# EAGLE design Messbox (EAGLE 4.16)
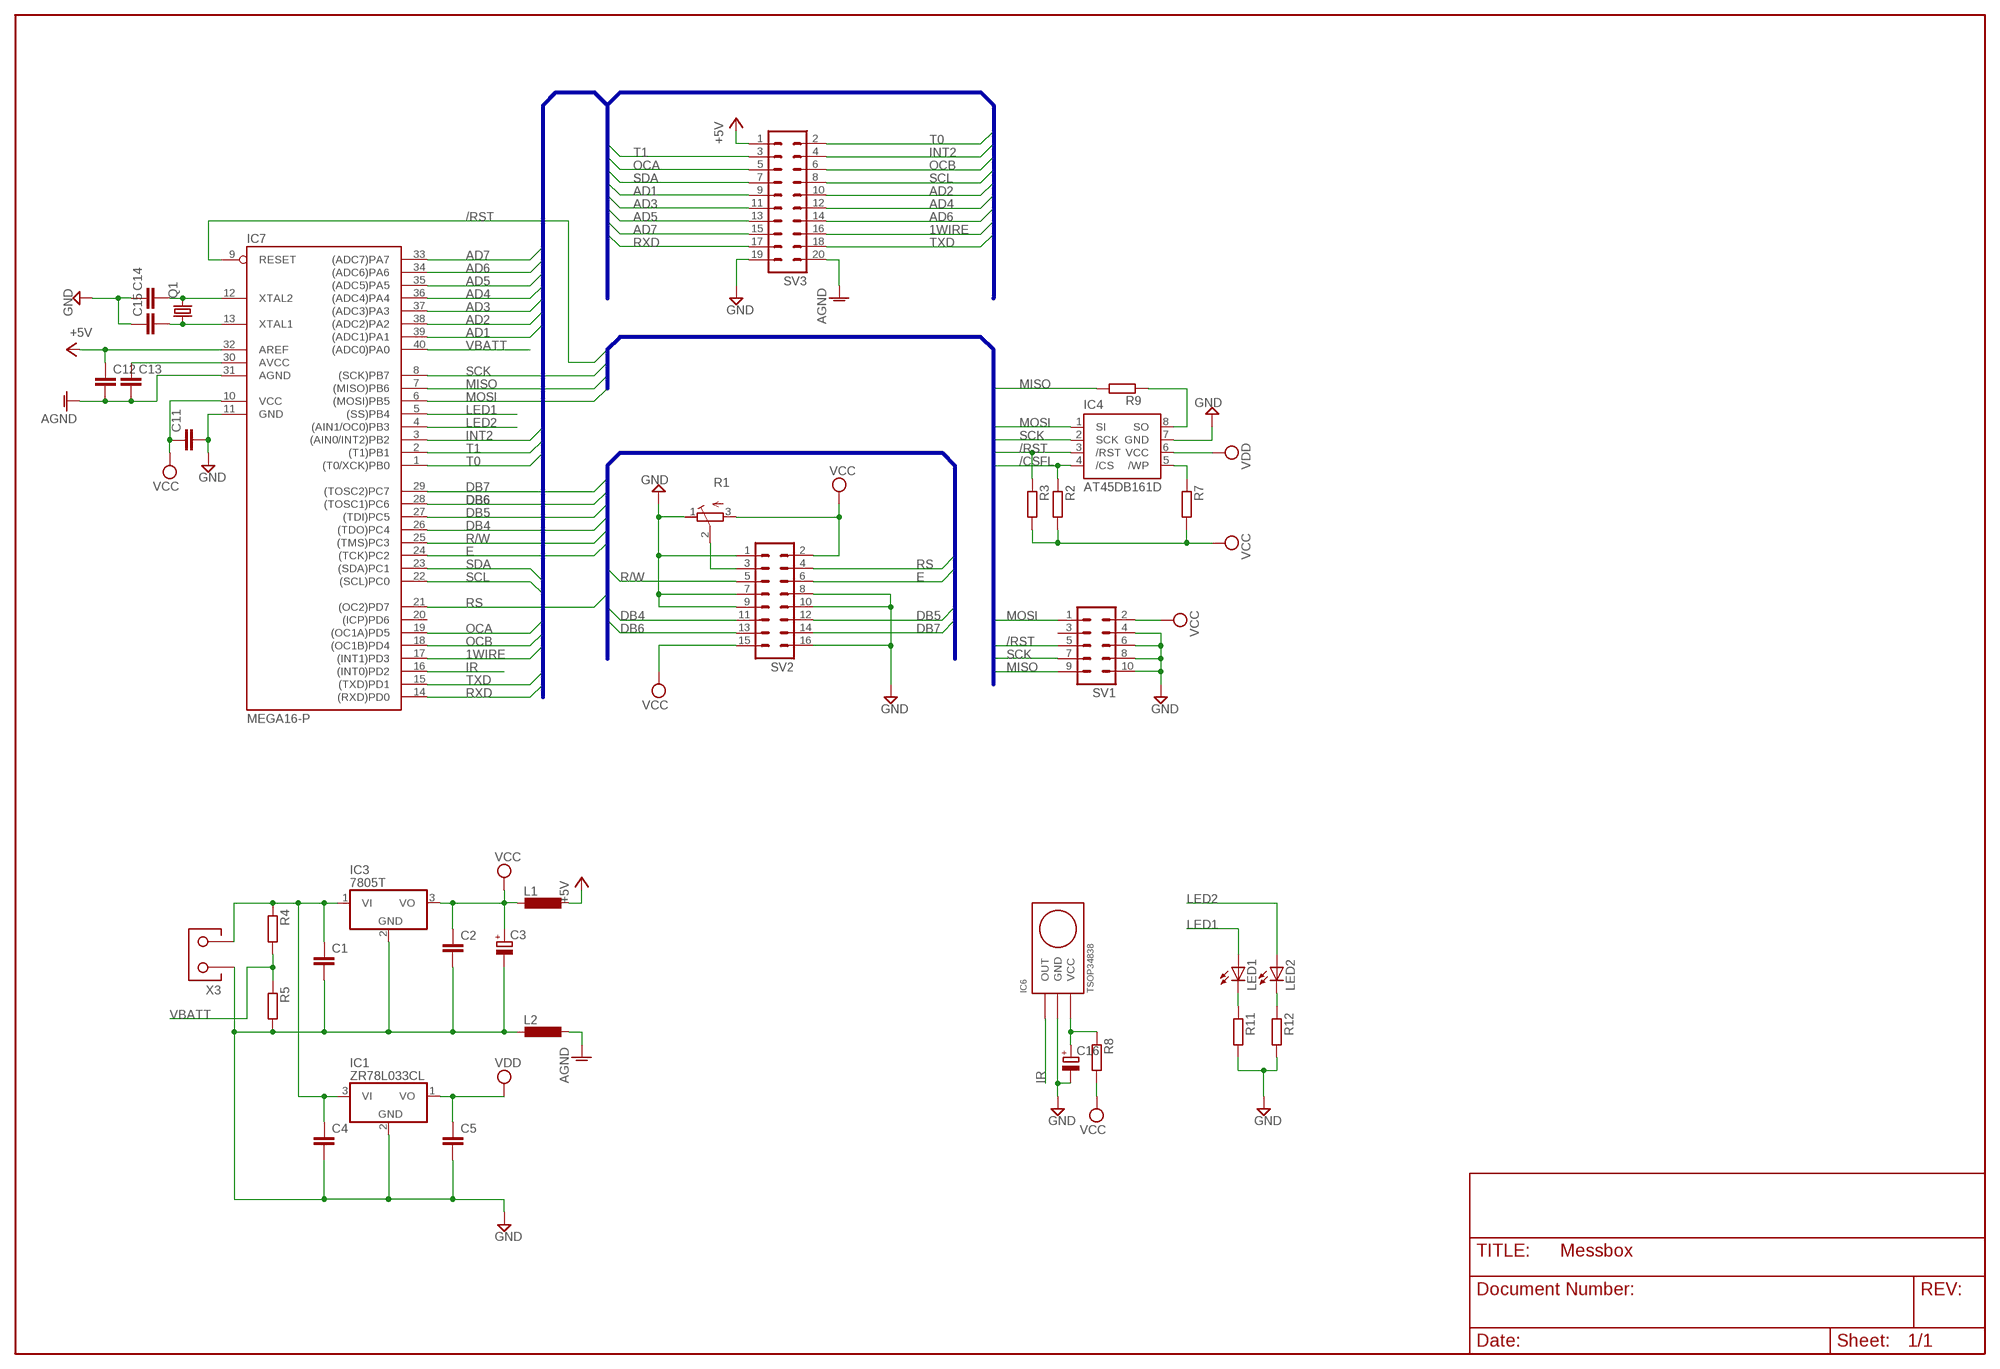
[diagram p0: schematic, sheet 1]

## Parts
C1  C-EUC1206K  [C1206K]
C2  C-EUC1206K  [C1206K]
C3  CPOL-EUE2.5-5  [E2,5-5]
C4  C-EUC1206K  [C1206K]
C5  C-EUC1206K  [C1206K]
C11  C-EUC1206K  [C1206K]
C12  C-EUC1206K  [C1206K]
C13  C-EUC1206K  [C1206K]
C14  C-EUC1206K  [C1206K]
C15  C-EUC1206K  [C1206K]
C16  CPOL-EUE2.5-5  [E2,5-5]
IC1  ZR78L033CL  [TO92]
IC3  7805T  [TO220H]
IC4  AT45DB161D  [SOIC8]
IC6  TSOP34838  [TSOP348]
IC7  MEGA16-P  [DIL40]
L1  L-EU0207/10  [0207/10]
L2  L-EU0207/10  [0207/10]
LED1  LED5MM  [LED5MM]
LED2  LED5MM  [LED5MM]
Q1  CRYTALHC49U-V  [HC49U-V]
R1  R-TRIMMT93YB  [RTRIMT93YB]
R2  R-EU_0207/10  [0207/10]
R3  R-EU_0207/10  [0207/10]
R4  R-EU_0207/10  [0207/10]
R5  R-EU_0207/10  [0207/10]
R7  R-EU_0207/10  [0207/10]
R8  R-EU_0207/10  [0207/10]
R9  R-EU_0207/10  [0207/10]
R11  R-EU_0207/10  [0207/10]
R12  R-EU_0207/10  [0207/10]
SV1  ML10  [ML10]
SV2  ML16  [ML16]
SV3  ML20  [ML20]
X3  AKL-2_3,5  [AKL-2_3,5]

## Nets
1WIRE: IC7.17((INT1)PD3) SV3.16
+5V: C12.1 IC7.32(AREF) L1.1 SV3.1
/CSFL: IC4.4(/CS) R2.1
/RST: IC4.3(/RST) IC7.9(RESET) R3.1 SV1.5
AD1: IC7.39((ADC1)PA1) SV3.9
AD2: IC7.38((ADC2)PA2) SV3.10
AD3: IC7.37((ADC3)PA3) SV3.11
AD4: IC7.36((ADC4)PA4) SV3.12
AD5: IC7.35((ADC5)PA5) SV3.13
AD6: IC7.34((ADC6)PA6) SV3.14
AD7: IC7.33((ADC7)PA7) SV3.15
AGND: C12.2 C13.2 IC7.31(AGND) L2.1 SV3.20
DB4: IC7.26((TDO)PC4) SV2.11
DB5: IC7.27((TDI)PC5) SV2.12
DB6: IC7.28((TOSC1)PC6) SV2.13
DB7: IC7.29((TOSC2)PC7) SV2.14
E: IC7.24((TCK)PC2) SV2.6
GND: C1.2 C2.2 C3.- C4.2 C5.2 C11.2 C14.1 C15.1 C16.- IC1.2(GND) IC3.2(GND) IC4.7(GND) IC6.P$2(GND) IC7.11(GND) L2.2 R1.1(A) R5.2 R11.2 R12.2 SV1.4 SV1.6 SV1.8 SV1.10 SV2.1 SV2.7 SV2.8 SV2.9 SV2.10 SV2.16 SV3.19 X3.P$1
INT2: IC7.3((AIN0/INT2)PB2) SV3.4
IR: IC6.P$1(OUT) IC7.16((INT0)PD2)
LED1: IC7.5((SS)PB4) LED1.A
LED2: IC7.4((AIN1/OC0)PB3) LED2.A
MISO: IC7.7((MISO)PB6) R9.2 SV1.9
MOSI: IC4.1(SI) IC7.6((MOSI)PB5) SV1.1
N$1: LED2.K(C) R12.1
N$3: LED1.K(C) R11.1
N$4: R1.2(S) SV2.3
N$14: IC4.8(SO) R9.1
N$18: C16.+ IC6.P$3(VCC) R8.1
N$20: C1.1 C4.1 IC1.3(VI) IC3.1(VI) R4.1 X3.P$2
N$21: C15.2 IC7.13(XTAL1) Q1.1
N$23: C14.2 IC7.12(XTAL2) Q1.2
N$42: IC4.5(/WP) R7.1
N$46: C13.1 IC7.30(AVCC)
OCA: IC7.19((OC1A)PD5) SV3.5
OCB: IC7.18((OC1B)PD4) SV3.6
R/W: IC7.25((TMS)PC3) SV2.5
RS: IC7.21((OC2)PD7) SV2.4
RXD: IC7.14((RXD)PD0) SV3.17
SCK: IC4.2(SCK) IC7.8((SCK)PB7) SV1.7
SCL: IC7.22((SCL)PC0) SV3.8
SDA: IC7.23((SDA)PC1) SV3.7
T0: IC7.1((T0/XCK)PB0) SV3.2
T1: IC7.2((T1)PB1) SV3.3
TXD: IC7.15((TXD)PD1) SV3.18
VBATT: IC7.40((ADC0)PA0) R4.2 R5.1
VCC: C2.1 C3.+ C11.1 IC3.3(VO) IC7.10(VCC) L1.2 R1.3(E) R2.2 R3.2 R7.2 R8.2 SV1.2 SV2.2 SV2.15
VDD: C5.1 IC1.1(VO) IC4.6(VCC)
Unconnected: IC7.20((ICP)PD6) SV1.3

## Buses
MOSI,MISO,SCK,/RST,/CSFL
RS,R/W,E,DB[4..7]
AD[0..7],OCA,OCB,RXD,TXD,SDA,SCL,1WIRE,T0,T1,INT2

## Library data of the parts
C1 C2 C4 C5 C11-C15 = rcl:C-EU: CAPACITOR, European symbol
C3 C16 = rcl:CPOL-EU: POLARIZED CAPACITOR, European symbol
IC1 = 0mylib:ZR78L033C: Positive VOLTAGE REGULATOR Source: http://cache.national.com/ds/LM/LM78L05.pdf http://www.fairchildsemi.com/ds/LM/LM7805.pdf
IC3 = linear:78*: Positive VOLTAGE REGULATOR
IC4 = 0mylib:AT45DB161D
IC6 = 0mylib:TSOP34838
IC7 = avr:MEGA16-P: MICROCONTROLLER 16 Kbytes FLASH 1 kbytes SRAM 512 bytes EEPROM USART 8-channel 10 bit ADC
L1 L2 = rcl:L-EU: INDUCTOR, European symbol
LED1 LED2 = led:LED: LED
Q1 = crystal:CRYTAL: CRYSTAL
R1 = rcl:R-TRIMM: Trimm resistor
R2-R5 R7-R9 R11 R12 = rcl:R-EU_: RESISTOR, European symbol
SV1 = con-harting-ml:ML10: HARTING
SV2 = con-harting-ml:ML16: HARTING
SV3 = con-harting-ml:ML20: HARTING
X3 = 0mylib:AKL-2_3,5

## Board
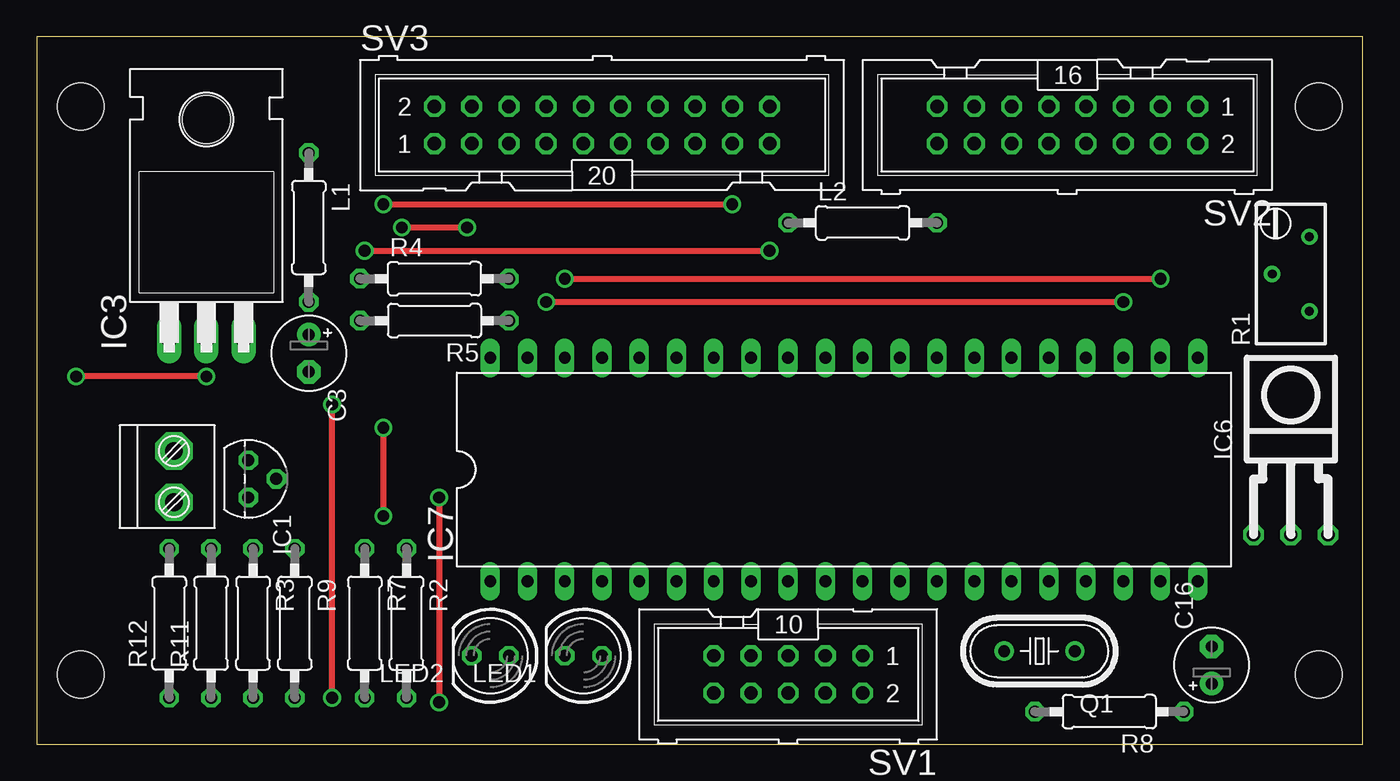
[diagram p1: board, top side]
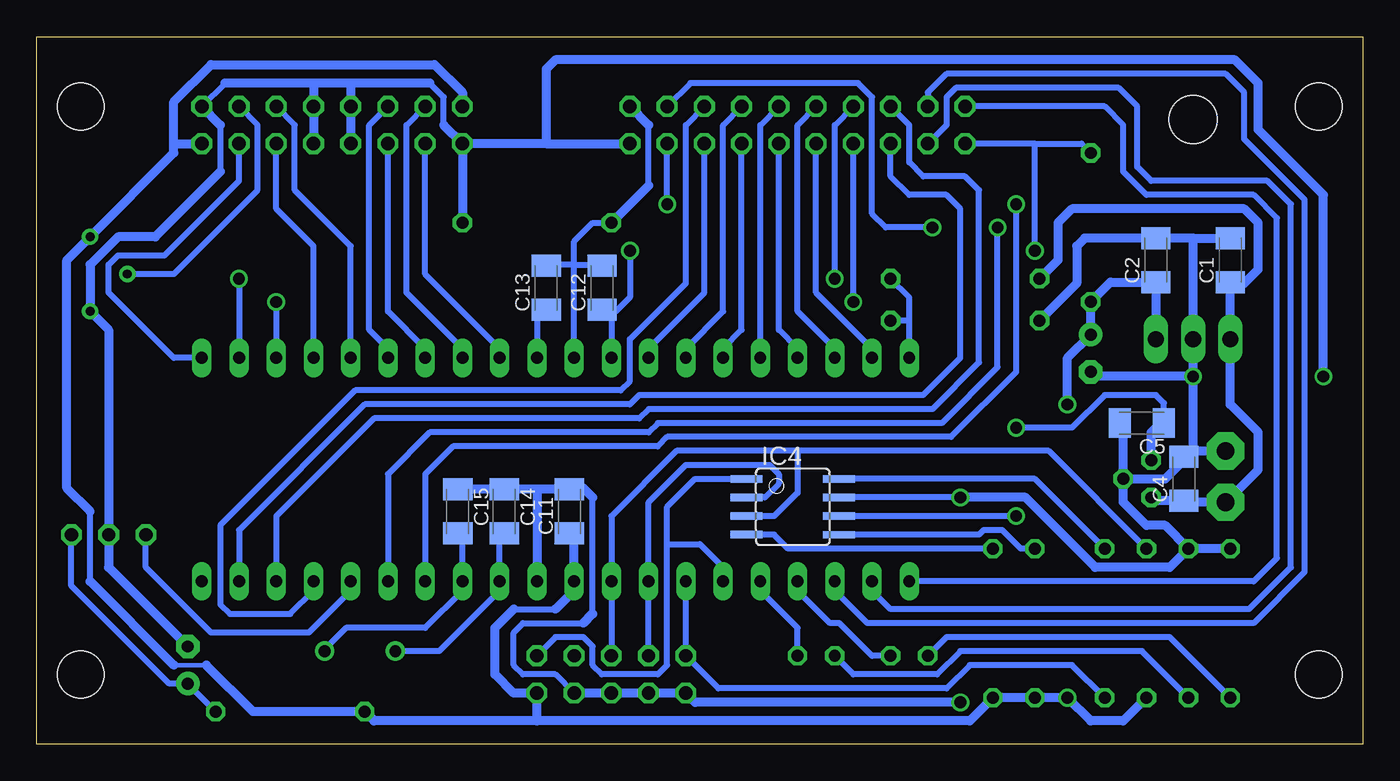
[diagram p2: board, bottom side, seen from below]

Size 90.47 x 48.25 mm. Coordinates in mm from the lower left corner, seen from the top.
Outline: 0,0 90.47,0 90.47,48.25 0,48.25 0,0
Copper layers (1*16): Top 0.035mm / dielectric 1.5mm / Bottom 0.035mm
Design rules "default": minimum track width 10mil, minimum drill 24mil, track to track 12mil, track to pad 12mil, pad to pad 12mil, via to via 12mil, smd to smd 12mil, copper to edge 40mil, drill to drill 8mil, minimum pad ring 10mil, minimum via ring 8mil, stop-mask expansion 4mil, vias tented up to drill 0mil, thermal gap 10mil
Holes 3.2 mm at 87.46,4.76 3.01,43.49 87.46,43.49 3.01,4.76

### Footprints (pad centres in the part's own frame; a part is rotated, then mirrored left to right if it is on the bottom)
C1206K = smd 1.5 x 2: 1 -1.5,0; 2 1.5,0
E2,5-5 = drill 0.813 pad 1.6 round: + -1.27,0 | drill 0.813 pad 1.6 octagon: - 1.27,0
TO92 = drill 0.813 octagon: 1 -1.27,0; 2 0,1.905; 3 1.27,0
TO220H = drill 1.118 long: 1 -2.54,-10.16; 2 0,-10.16; 3 2.54,-10.16 | hole 3.302: 0,4.826
SOIC8 = smd 0.5 x 2.2: 1 -1.905,-3.154; 2 -0.645,-3.154; 3 0.625,-3.154; 4 1.895,-3.154; 5 1.905,3.154; 6 0.635,3.154; 7 -0.635,3.154; 8 -1.905,3.154
TSOP348 = drill 0.9 octagon: P$1 -5.08,2.54; P$2 -5.08,0; P$3 -5.08,-2.54
DIL40 = drill 0.813 long: 1 -24.13,-7.62; 2 -21.59,-7.62; 3 -19.05,-7.62; 4 -16.51,-7.62; 5 -13.97,-7.62; 6 -11.43,-7.62; 7 -8.89,-7.62; 8 -6.35,-7.62; 9 -3.81,-7.62; 10 -1.27,-7.62; 11 1.27,-7.62; 12 3.81,-7.62; 13 6.35,-7.62; 14 8.89,-7.62; 15 11.43,-7.62; 16 13.97,-7.62; 17 16.51,-7.62; 18 19.05,-7.62; 19 21.59,-7.62; 20 24.13,-7.62; 21 24.13,7.62; 22 21.59,7.62; 23 19.05,7.62; 24 16.51,7.62; 25 13.97,7.62; 26 11.43,7.62; 27 8.89,7.62; 28 6.35,7.62; 29 3.81,7.62; 30 1.27,7.62; 31 -1.27,7.62; 32 -3.81,7.62; 33 -6.35,7.62; 34 -8.89,7.62; 35 -11.43,7.62; 36 -13.97,7.62; 37 -16.51,7.62; 38 -19.05,7.62; 39 -21.59,7.62; 40 -24.13,7.62
0207/10 = drill 0.813 octagon: 1 -5.08,0; 2 5.08,0
LED5MM = drill 0.813 octagon: A -1.27,0; K 1.27,0
HC49U-V = drill 0.813 round: 1 -2.413,0; 2 2.413,0
RTRIMT93YB = drill 0.61 round: 1 1.27,-2.54; 2 -1.27,0; 3 1.27,2.54
ML10 = drill 0.914 octagon: 1 -5.08,-1.27; 2 -5.08,1.27; 3 -2.54,-1.27; 4 -2.54,1.27; 5 0,-1.27; 6 0,1.27; 7 2.54,-1.27; 8 2.54,1.27; 9 5.08,-1.27; 10 5.08,1.27
ML16 = drill 0.914 octagon: 1 -8.89,-1.27; 2 -8.89,1.27; 3 -6.35,-1.27; 4 -6.35,1.27; 5 -3.81,-1.27; 6 -3.81,1.27; 7 -1.27,-1.27; 8 -1.27,1.27; 9 1.27,-1.27; 10 1.27,1.27; 11 3.81,-1.27; 12 3.81,1.27; 13 6.35,-1.27; 14 6.35,1.27; 15 8.89,-1.27; 16 8.89,1.27
ML20 = drill 0.914 octagon: 1 -11.43,-1.27; 2 -11.43,1.27; 3 -8.89,-1.27; 4 -8.89,1.27; 5 -6.35,-1.27; 6 -6.35,1.27; 7 -3.81,-1.27; 8 -3.81,1.27; 9 -1.27,-1.27; 10 -1.27,1.27; 11 1.27,-1.27; 12 1.27,1.27; 13 3.81,-1.27; 14 3.81,1.27; 15 6.35,-1.27; 16 6.35,1.27; 17 8.89,-1.27; 18 8.89,1.27; 19 11.43,-1.27; 20 11.43,1.27
AKL-2_3,5 = drill 1.2 pad 2.54 octagon: P$1 0,0; P$2 3.5,0

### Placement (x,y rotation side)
C1  9.04,33.02 90 bottom
C2  14.12,33.02 90 bottom
C3  18.57,26.67 270 top
C4  12.22,18.09 90 bottom
C5  15.08,21.9 180 bottom
C11  54.13,15.87 90 bottom
C12  51.91,31.11 90 bottom
C13  55.72,31.11 90 bottom
C14  58.57,15.87 270 bottom
C15  61.75,15.87 270 bottom
C16  80.16,5.39 90 top
IC1  14.44,18.09 270 top
IC3  11.58,37.78 0 top
IC4  38.89,16.19 270 bottom
IC6  85.56,19.36 90 top
IC7  55.08,18.73 0 top
L1  18.57,35.24 270 top
L2  56.35,35.55 0 top
LED1  37.3,6.03 180 top
LED2  30.95,6.03 180 top
Q1  68.41,6.34 180 top
R1  85.56,32.06 0 top
R2  25.23,8.25 270 top
R3  14.76,8.25 270 top
R4  27.14,31.75 0 top
R5  27.14,28.89 180 top
R7  22.38,8.25 270 top
R8  73.18,2.22 180 top
R9  17.62,8.25 270 top
R11  11.9,8.25 90 top
R12  9.04,8.25 90 top
SV1  51.27,4.76 180 top
SV2  70.32,42.22 180 top
SV3  38.57,42.22 0 top
X3  9.36,20 270 top

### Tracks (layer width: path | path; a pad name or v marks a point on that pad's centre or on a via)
1WIRE
  Bottom 0.406: IC7.17 71.59,10.47 73.18,8.88 77.3,8.88 77.94,9.52 77.94,14.92 68.73,24.12 50.63,24.12 50,24.76 50,27.62 46.19,31.43 46.19,42.22 SV3.16
+5V  (via drill 0.8)
  Top 0.406: v22.38,33.65 v50,33.65
  Bottom 0.406: IC7.32 51.27,28.98 C12.1 51.91,29.21 51.59,29.52 50.95,29.52 50,30.48 v50,33.65 | L1.1 19.2,40.95 22.38,40.95 | 22.38,40.95 SV3.1 | v22.38,33.65 22.38,40.95
/CSFL
  Bottom 0.406: IC4.4 40.17,14.29 39.2,13.33 R2.1
/RST
  Bottom 0.406: 38.57,20 46.83,20 51.27,15.55 IC7.9 SV1.5 | 38.57,20 38.57,17.14 40.16,15.55 42.06,15.55 IC4.3 | R3.1 21.43,20 38.57,20
AD1
  Bottom 0.406: IC7.39 33.49,26.98 37.3,30.79 SV3.9
AD2
  Bottom 0.406: IC7.38 36.03,26.98 38.57,29.52 38.57,42.22 SV3.10
AD3
  Bottom 0.406: IC7.37 38.57,26.98 39.84,28.25 SV3.11
AD4
  Bottom 0.406: IC7.36 41.11,42.22 SV3.12
AD5
  Bottom 0.406: IC7.35 43.65,26.98 42.38,28.25 SV3.13
AD6
  Bottom 0.406: IC7.34 46.19,26.98 43.65,29.52 43.65,42.22 SV3.14
AD7
  Bottom 0.406: IC7.33 48.73,26.98 44.92,30.79 SV3.15
AGND
  Bottom 0.406: IC7.31 53.81,32.7 | C13.2 55.72,32.7 53.81,32.7 | C12.2 51.99,32.7 53.81,32.7 | 53.81,32.7 53.81,34.28 52.54,35.55 L2.1 | 48.73,38.09 48.73,42.22
  Bottom 0.61: 48.73,42.22 SV3.20 | L2.1 48.73,38.09
DB4
  Bottom 0.406: SV2.11 67.78,42.22 67.78,28.25 66.51,26.98 IC7.26
DB5
  Bottom 0.406: IC7.27 63.97,26.98 66.51,29.52 SV2.12
DB6
  Bottom 0.406: SV2.13 65.24,42.22 65.24,30.79 61.43,26.98 IC7.28
DB7
  Bottom 0.406: SV2.14 63.97,32.06 58.89,26.98 IC7.29
E
  Bottom 0.406: IC7.24 71.59,33.97 74.13,36.51 SV2.6
GND  (via drill 0.8)
  Top 0.406: v27.46,16.82 v27.46,2.85 | v11.58,25.08 v2.69,25.08
  Bottom 0.406: 77.62,45.08 SV2.1 | v27.46,16.82 IC4.7 | IC7.11 56.35,10.47 | 62.7,42.22 62.7,44.13 63.65,45.08 | 77.94,42.22 77.94,39.05 | C14.1 58.57,17.46 58.48,17.37 | C15.1 61.75,17.14 61.52,17.37 | 56.35,17.37 56.35,17.46 | SV1.4 55.08,4.76 57.3,4.76 57.94,5.39 57.94,7.62 57.3,8.25 53.18,8.25 | 52.54,8.88 52.54,16.82 | C11.2 54.13,17.14 53.81,17.46 53.18,17.46 | 12.22,19.68 C4.2 12.22,19.36 | C5.2 16.66,21.9 16.35,21.59 | C2.2 14.12,34.6 14.04,34.52
  Bottom 0.61: SV1.4 SV1.6 SV1.8 SV1.10 45.55,2.85 v27.46,2.85 | R12.2 R11.2 | R11.2 13.17,12.06 18.25,12.06 23.01,16.82 v27.46,16.82 | 55.72,40.95 SV3.19 | 55.72,40.95 SV2.16 | SV2.16 62.7,42.22 | SV2.10 SV2.9 69.05,45.08 | SV2.8 SV2.7 71.59,45.08 | 71.59,45.08 77.62,45.08 | 69.05,45.08 71.59,45.08 | 63.65,45.08 69.05,45.08 | SV2.1 77.94,42.22 | 77.94,39.05 82.38,34.6 84.92,34.6 86.83,32.7 R1.1 85.56,28.25 IC6.P$2 85.56,12.06 C16.- | C11.2 56.35,17.37 | 56.35,17.37 58.48,17.37 | C14.1 61.52,17.37 | 56.35,17.37 IC7.11 | 53.18,8.25 52.54,8.88 | 52.54,16.82 53.18,17.46 | 11.58,20 X3.P$1 | 11.58,20 11.58,19.68 12.22,19.68 | 12.22,19.36 13.49,18.09 IC1.2 | IC1.2 16.35,21.59 | R11.2 13.49,14.92 14.76,14.92 16.35,16.51 IC1.2 | R5.2 19.52,31.43 19.52,33.97 18.97,34.52 C2.2 | v2.69,25.08 2.69,37.46 7.14,41.9 7.14,45.08 8.73,46.67 55.08,46.67 55.72,46.03 55.72,40.95 | 11.58,20 v11.58,25.08 | C3.- 18.25,25.08 v11.58,25.08 | SV2.16 L2.2 | 11.58,34.52 C1.2 | 11.58,34.52 14.04,34.52 | 11.58,34.52 IC3.2 v11.58,25.08
INT2
  Bottom 0.406: IC7.3 36.03,10.47 33.81,8.25 7.46,8.25 3.96,11.74 3.96,37.14 8.09,41.27 8.09,44.45 9.36,45.71 28.41,45.71 29.68,44.45 SV3.4
IR
  Bottom 0.406: IC6.P$1 83.02,12.06 78.57,7.62 71.91,7.62 69.05,10.47 IC7.16
LED1
  Bottom 0.406: LED1.A 38.57,7.93 41.11,10.47 IC7.5
LED2
  Bottom 0.406: IC7.4 38.57,10.47 36.35,8.25 35.71,8.25 33.49,6.03 LED2.A
MISO
  Bottom 0.406: IC7.7 SV1.9 43.97,3.81 28.41,3.81 26.82,5.39 19.84,5.39 R9.2
MOSI
  Bottom 0.406: SV1.1 55.08,7.3 53.18,7.3 52.54,6.66 52.54,5.39 51.91,4.76 48.09,4.76 47.46,5.39 47.46,13.65 | IC4.1 45.55,18.09 47.46,16.19 47.46,13.65 | 47.46,13.65 45.24,13.65 43.65,12.06 IC7.6
N$1
  Bottom 0.406: LED2.K 28.41,7.3 13.17,7.3 R12.1
N$3
  Bottom 0.406: LED1.K 34.76,4.76 29.05,4.76 27.46,6.34 15.08,6.34 R11.1
N$4
  Bottom 0.406: R1.2 81.11,32.06 75.4,37.78 75.4,42.22 SV2.3
N$14
  Bottom 0.406: IC4.8 22.38,18.09 R9.1
N$18
  Bottom 0.406: IC6.P$3 88.1,10.79 81.43,4.12 C16.+ R8.1
N$20
  Bottom 0.406: X3.P$2 | C4.1 12.22,16.51 12.21,16.5
  Bottom 0.61: X3.P$2 7.14,18.73 7.14,21.27 9.04,23.17 IC3.1 9.04,31.43 | X3.P$2 12.21,16.5 | C4.1 14.21,16.59 IC1.3 | 9.04,31.43 C1.1 | R4.1 20.79,33.02 20.79,35.55 19.84,36.51 8.09,36.51 7.14,35.55 7.14,32.38 8.09,31.43 9.04,31.43
N$21
  Bottom 0.406: C15.2 61.75,14.28 61.43,13.96 IC7.13 61.43,10.47 63.97,7.93 69.37,7.93 70.95,6.34 Q1.1
N$23
  Bottom 0.406: Q1.2 63.02,6.34 58.89,10.47 IC7.12 58.89,13.96 58.57,14.28 C14.2
N$42
  Bottom 0.406: IC4.5 26.19,14.28 25.87,14.6 24.6,14.6 23.33,13.33 R7.1
N$46
  Bottom 0.406: C13.1 56.35,28.98 IC7.30
OCA
  Bottom 0.406: IC7.19 76.67,14.6 68.1,23.17 50,23.17 49.37,23.81 30,23.81 27.46,26.35 27.46,36.51 28.41,37.46 30.95,37.46 32.22,38.73 SV3.5
OCB
  Bottom 0.406: IC7.18 74.13,15.55 67.46,22.22 49.37,22.22 48.73,22.86 29.36,22.86 26.19,26.03 26.19,37.78 27.14,38.73 30,38.73 30.95,39.68 30.95,42.22 SV3.6
R/W
  Bottom 0.406: IC7.25 69.05,33.97 72.86,37.78 72.86,42.22 SV2.5
RS
  Bottom 0.406: SV2.4 76.67,38.41 81.75,33.33 84.92,33.33 85.56,32.7 85.56,30.79 81.11,26.35 IC7.21
RXD  (via drill 0.8)
  Top 0.406: v23.65,36.82 v47.46,36.82
  Bottom 0.406: IC7.14 63.97,18.41 62.06,20.32 48.09,20.32 47.46,20.95 28.09,20.95 23.65,25.39 v23.65,36.82 | v47.46,36.82 SV3.17
SCK
  Bottom 0.406: IC4.2 40.8,16.83 40.79,16.82 39.84,17.78 39.84,18.41 40.48,19.05 46.19,19.05 48.73,16.51 IC7.8 SV1.7
SCL  (via drill 0.8)
  Top 0.406: v36.03,31.75 v76.67,31.75
  Bottom 0.406: v76.67,31.75 IC7.22 | v36.03,31.75 36.03,42.22 SV3.8
SDA  (via drill 0.8)
  Top 0.406: v34.76,30.16 v74.13,30.16
  Bottom 0.406: v74.13,30.16 IC7.23 | v34.76,30.16 SV3.7
T0
  Bottom 0.406: IC7.1 7.46,11.11 5.87,12.69 5.87,35.87 7.46,37.46 14.76,37.46 16.35,39.05 16.35,42.22 17.62,43.49 SV3.2
T1
  Bottom 0.406: SV3.3 28.41,42.22 28.41,44.13 27.78,44.76 16.66,44.76 15.39,43.49 15.39,39.36 14.44,38.41 6.5,38.41 4.92,36.82 4.92,12.06 7.77,9.2 32.22,9.2 33.49,10.47 IC7.2
TXD  (via drill 0.8)
  Top 0.406: v24.92,35.24 v29.36,35.24
  Bottom 0.406: IC7.15 66.51,18.41 63.65,21.27 48.73,21.27 48.09,21.9 28.73,21.9 24.92,25.71 v24.92,35.24 | v29.36,35.24 32.54,35.24 33.49,36.19 33.49,44.13 34.44,45.08 45.87,45.08 SV3.18
VBATT
  Bottom 0.406: IC7.40 30.95,28.89 | 30.95,28.89 30.95,30.48 R4.2 | 30.95,28.89 R5.1
VCC  (via drill 0.8)
  Top 0.406: v20.16,3.17 v20.16,23.17
  Bottom 0.305: 78.89,5.39 81.11,5.39
  Bottom 0.406: 57.94,9.2 55.08,9.2 | 53.81,10.47 IC7.10 | C11.1 54.13,14.28 53.81,13.96 | L1.2 18.25,30.48 | IC3.3 14.76,28.25 | 86.83,11.11 86.83,15.87
  Bottom 0.61: 56.35,1.58 26.82,1.58 R2.2 R7.2 v20.16,3.17 18.57,1.58 16.35,1.58 R3.2 | 57.94,9.2 59.21,7.93 59.21,4.76 57.94,3.49 SV1.2 56.35,1.58 | 55.08,9.2 53.81,10.47 | 81.11,40.95 81.11,40.32 R1.3 88.42,33.02 88.42,17.46 86.83,15.87 | 81.11,40.95 SV2.2 | SV2.15 61.43,44.45 63.34,46.35 78.57,46.35 81.11,43.81 81.11,40.95 | IC7.10 53.81,13.96 | IC3.3 C2.1 17.21,31.52 18.25,30.48 | v20.16,23.17 20.16,26.35 C3.+ L1.2 | 56.35,1.58 67.46,1.58 R8.2 75.72,2.22 78.89,5.39 | 81.11,5.39 86.83,11.11
VDD  (via drill 0.8)
  Top 0.406: v23.65,21.59 v23.65,15.55
  Bottom 0.406: 13.81,21.9 C5.1 13.58,23.26 14.12,23.81 17.62,23.81 19.84,21.59 v23.65,21.59 | v23.65,15.55 IC4.6
  Bottom 0.61: IC1.1 14.44,21.27 13.81,21.9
